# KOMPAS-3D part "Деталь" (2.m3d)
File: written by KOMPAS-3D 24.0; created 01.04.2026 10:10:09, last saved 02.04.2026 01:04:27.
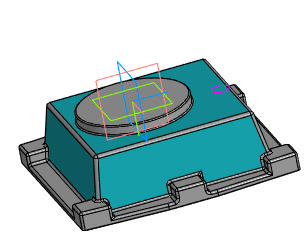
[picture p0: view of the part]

Document properties: Автор: R2D2; Полное имя файла: E:\Работа\Зайцев\Аксессуары для пневмоприводов\Блок концевых выключателей DN.ru\APL-410N EX Блок концевых выключателей DN.ru\исходные материалы\2.m3d

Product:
- Part/product: Деталь
    Масса: 8.540824

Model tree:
1. Эскиз:1
2. Элемент выдавливания:1
     Расстояние 1 = 8
3. Эскиз:2
4. Элемент выдавливания:2
     Расстояние 1 = 8
5. Уклон:1  (with: Грань.Элемент выдавливания:1)
     Угол уклона = 15
6. Уклон:3  (with: Грань.Элемент выдавливания:2)
     Угол уклона = 15
7. Массив по концентрической сетке:1  (2 pattern instances)
8. Тело 2  (2 pattern instances)
     N 1 = 1; Шаг 1 = 10; Шаг 2 = 360; Номер 1 = 1
9. Эскиз:3  (with: Грань.Элемент выдавливания:1)
10. Элемент выдавливания:3
     Расстояние 1 = 50
11. Эскиз:7  (with: Грань.Элемент выдавливания:3, Ребро.Элемент выдавливания:2)  (labels: Ребро.Тело 2.Экземпляр ( 1, 3 ))
12. Элемент выдавливания:6  (with: Грань.Элемент выдавливания:2, Массив по концентрической сетке:1, Эскиз:7, Грань.Уклон:1)  (4 pattern instances)
     Расстояние 1 = 8; N 1 = 1; Шаг 1 = 10; Шаг 2 = 360; Номер 1 = 1
13. Эскиз:9  (labels: Грань.Тело 2.Экземпляр ( 1, 3 ); Ребро.Тело 2.Экземпляр ( 1, 2 ))
14. Элемент выдавливания:8
     Расстояние 2 = 10
15. Эскиз:10  (labels: Грань.Тело 2.Экземпляр ( 1, 3 ))
16. Элемент выдавливания:9
     Расстояние 1 = 24
17. Эскиз:11  (with: Грань.Элемент выдавливания:9)
18. Элемент выдавливания:10
     Расстояние 1 = 3
19. Эскиз:12  (with: Грань.Элемент выдавливания:10)
20. Элемент выдавливания:11
     Расстояние 2 = 7
21. Фаска:2  (with: Ребро.Элемент выдавливания:10, Ребро.Элемент выдавливания:9)
     Угол = 45; Длина 1 = 0.5; Длина 2 = 0.5
22. Эскиз:13  (labels: Грань.Тело 2.Экземпляр ( 1, 3 ))
23. Элемент выдавливания:12
     Расстояние 1 = 1
24. Массив по концентрической сетке:3  (with: Элемент выдавливания:8, Эскиз:9, Грань.Элемент выдавливания:1)  (4 pattern instances)
     Шаг 2 = 360
25. Уклон:4  (with: Грань.Элемент выдавливания:3)
     Угол уклона = 10
26. Скругление:14  (with: Ребро.Элемент выдавливания:3, Грань.Элемент выдавливания:3)
     Радиус = 3
27. Эскиз:17  (with: Грань.Элемент выдавливания:3)
28. Элемент выдавливания:16
     Расстояние 2 = 5
29. Эскиз:18  (with: Грань.Элемент выдавливания:16, Вершина.Элемент выдавливания:16, Ребро.Элемент выдавливания:16)
30. Элемент выдавливания:17
     Расстояние 1 = 10
31. Эскиз:21  (with: Грань.Элемент выдавливания:3)
32. Элемент выдавливания:20
     Расстояние 1 = 35
33. Эскиз:22  (with: Грань.Элемент выдавливания:3)
34. Элемент выдавливания:21
     Расстояние 1 = 16
35. Скругление:21  (with: Ребро.Элемент выдавливания:16, Грань.Элемент выдавливания:17, Грань.Элемент выдавливания:16)
     Радиус = 2
36. Скругление:22  (with: Грань.Элемент выдавливания:21)
     Радиус = 1
37. Скругление:23  (with: Грань.Элемент выдавливания:16)
     Радиус = 0.5
38. Эскиз:23  (with: Грань.Элемент выдавливания:17)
